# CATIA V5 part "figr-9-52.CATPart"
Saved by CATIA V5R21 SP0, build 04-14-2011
Part number: Part1
Bounding box of the stored display mesh (mm): x -121 to 121, y -90 to 90, z -40 to 40
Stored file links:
  D:\CATIA V5R21 E-RESOURCES\CATIA-V5R21\catia-v5r21-prt\c09-catia-v5r20-prt\c09-catia-v5r21-figr-9-52.CATPart
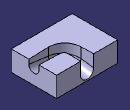
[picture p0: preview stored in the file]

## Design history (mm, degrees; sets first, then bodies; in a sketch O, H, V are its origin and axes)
Body1 (main body)
  Sketch1 on yz-plane, origin (0, 0, 0), H (0, 1, 0), V (0, 0, 1)
    line L1 (-90, 40) -> (90, 40)
    line L2 (90, 40) -> (90, -40)
    line L3 (90, -40) -> (-90, -40)
    line L4 (-90, -40) -> (-90, 40)
    axis line L5 (90, -40) -> (-90, 40)
    horizontal: L1 H, L3 H
    vertical: L2 V, L4 V
    midpoint: O L5
  Pad1: profile Sketch1, direction (1, 0, 0), length 121, mirrored extent
  Loft1: solid, Sections (Sketch4; Sketch3), Spine Sketch2, SectionCouplingPoints ({coupling CouplingPoints (vertex [element of Sketch4 | element of Sketch4]; vertex [element of Sketch3 | element of Sketch3])}; {coupling CouplingPoints (vertex [element of Sketch4 | element of Sketch4]; vertex [element of Sketch3 | element of Sketch3])}; {coupling CouplingPoints (vertex [element of Sketch4 | element of Sketch4]; vertex [element of Sketch3 | element of Sketch3])})
  Sketch2 on face of Pad1, origin (0, 0, 40), H (1, 0, 0), V (0, 1, 0)
    point P1 (121, 0)
    line L1 (121, 0) -> (40.984, 0)
    arc A1 centre (40.984, 40.984) radius 40.984 from (40.984, 0) to (0, 40.984) cw
    line L2 (0, 40.984) -> (0, 90)
    point P5 (0, 90)
    reference projected line E1 (121, 20) -> (121, -20) from edge of Sketch4
    reference projected line E2 (-25.9516, 90) -> (25.9516, 90) from edge of Sketch3
    coincidence: P1 H, P1 E1, P5 E2
    horizontal: L1 H
    tangency: A1 L1, L2 A1
    vertical: L2 V
  Sketch3 on face of Pad1, origin (0, 90, 0), H (-1, 0, 0), V (0, 0, 1)
    line L1 (-25.9516, 40) -> (-25.9516, -8.0968)
    arc A1 centre (0, -8.0968) radius 25.9516 from (-25.9516, -8.0968) to (25.9516, -8.0968) ccw
    point P3 (0, -8.0968)
    line L2 (25.9516, -8.0968) -> (25.9516, 40)
    line L3 (25.9516, 40) -> (-25.9516, 40)
    reference projected line E1 (121, 40) -> (-121, 40) from edge [face of Pad1 | face of Pad1]
    vertical: L1 V, L2 V
    tangency: A1 L1, L2 A1
    horizontal: L3 H
    coincidence: P3 V, L3 E1
  Sketch4 on face of Pad1, origin (121, 0, 0), H (0, 1, 0), V (0, 0, 1)
    line L1 (-20, 40) -> (-20, 21.9917)
    arc A1 centre (0, 21.9917) radius 20 from (-20, 21.9917) to (20, 21.9917) ccw
    point P3 (0, 21.9917)
    line L2 (20, 21.9917) -> (20, 40)
    line L3 (20, 40) -> (-20, 40)
    reference projected line E1 (90, 40) -> (-90, 40) from edge [face of Pad1 | face of Pad1]
    vertical: L1 V, L2 V
    tangency: A1 L1, L2 A1
    horizontal: L3 H
    coincidence: P3 V, L3 E1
